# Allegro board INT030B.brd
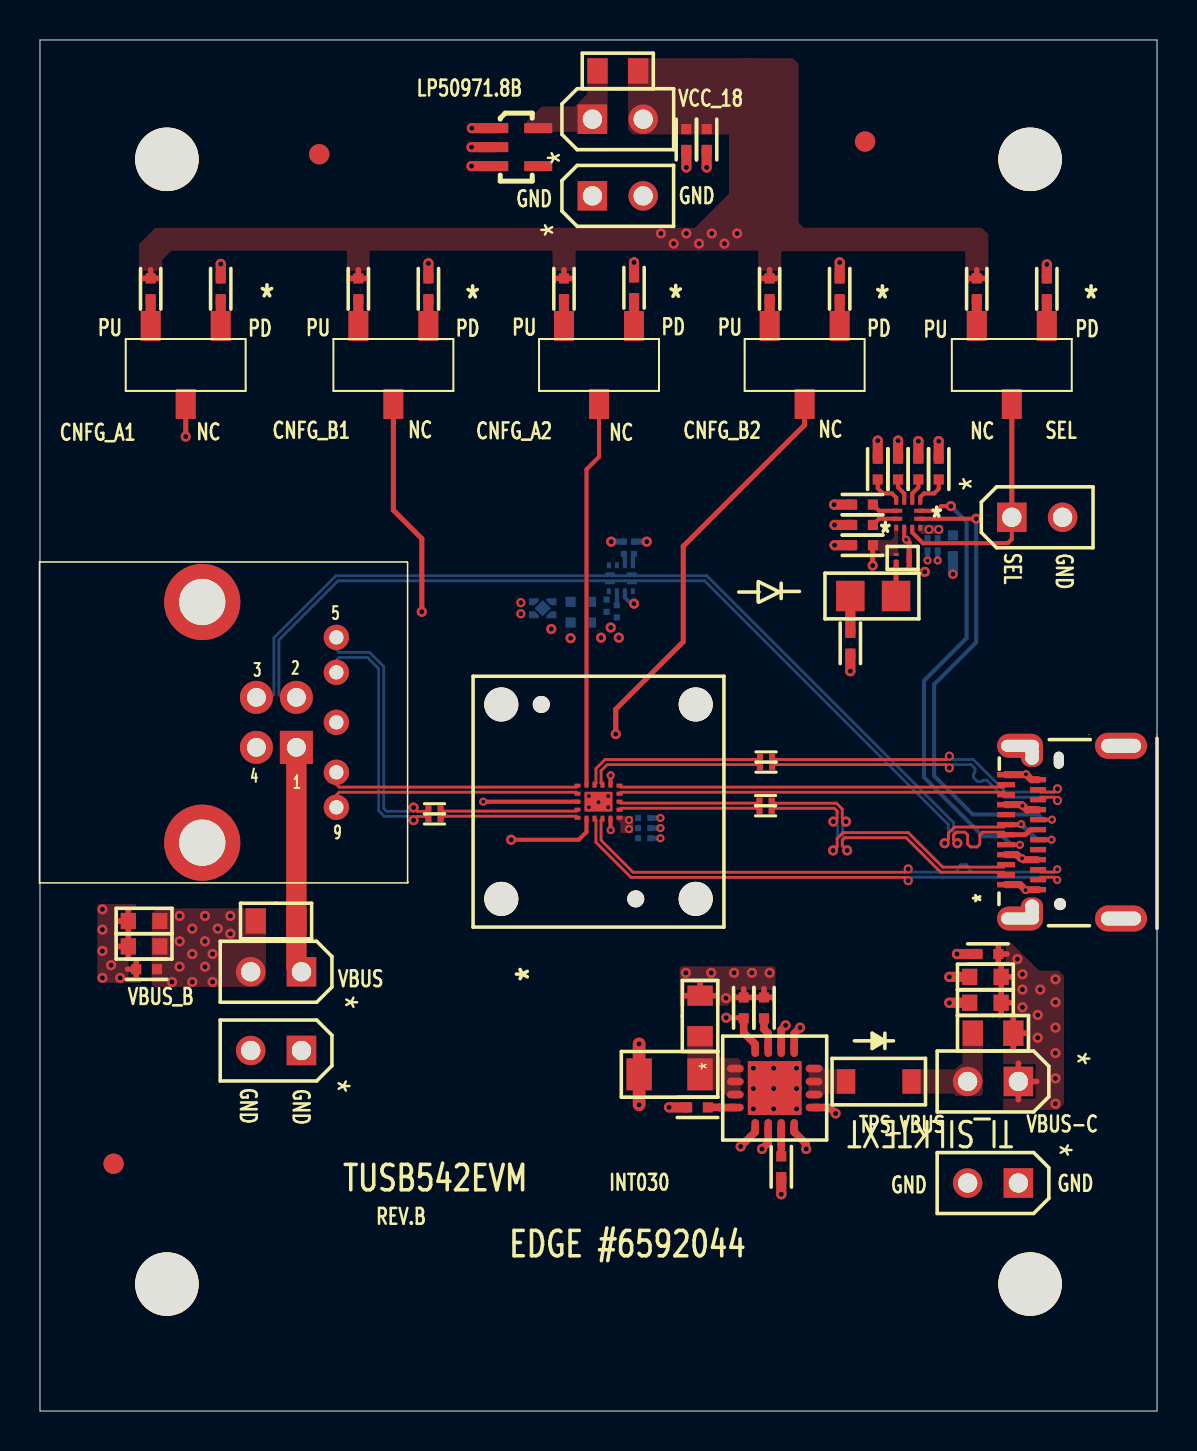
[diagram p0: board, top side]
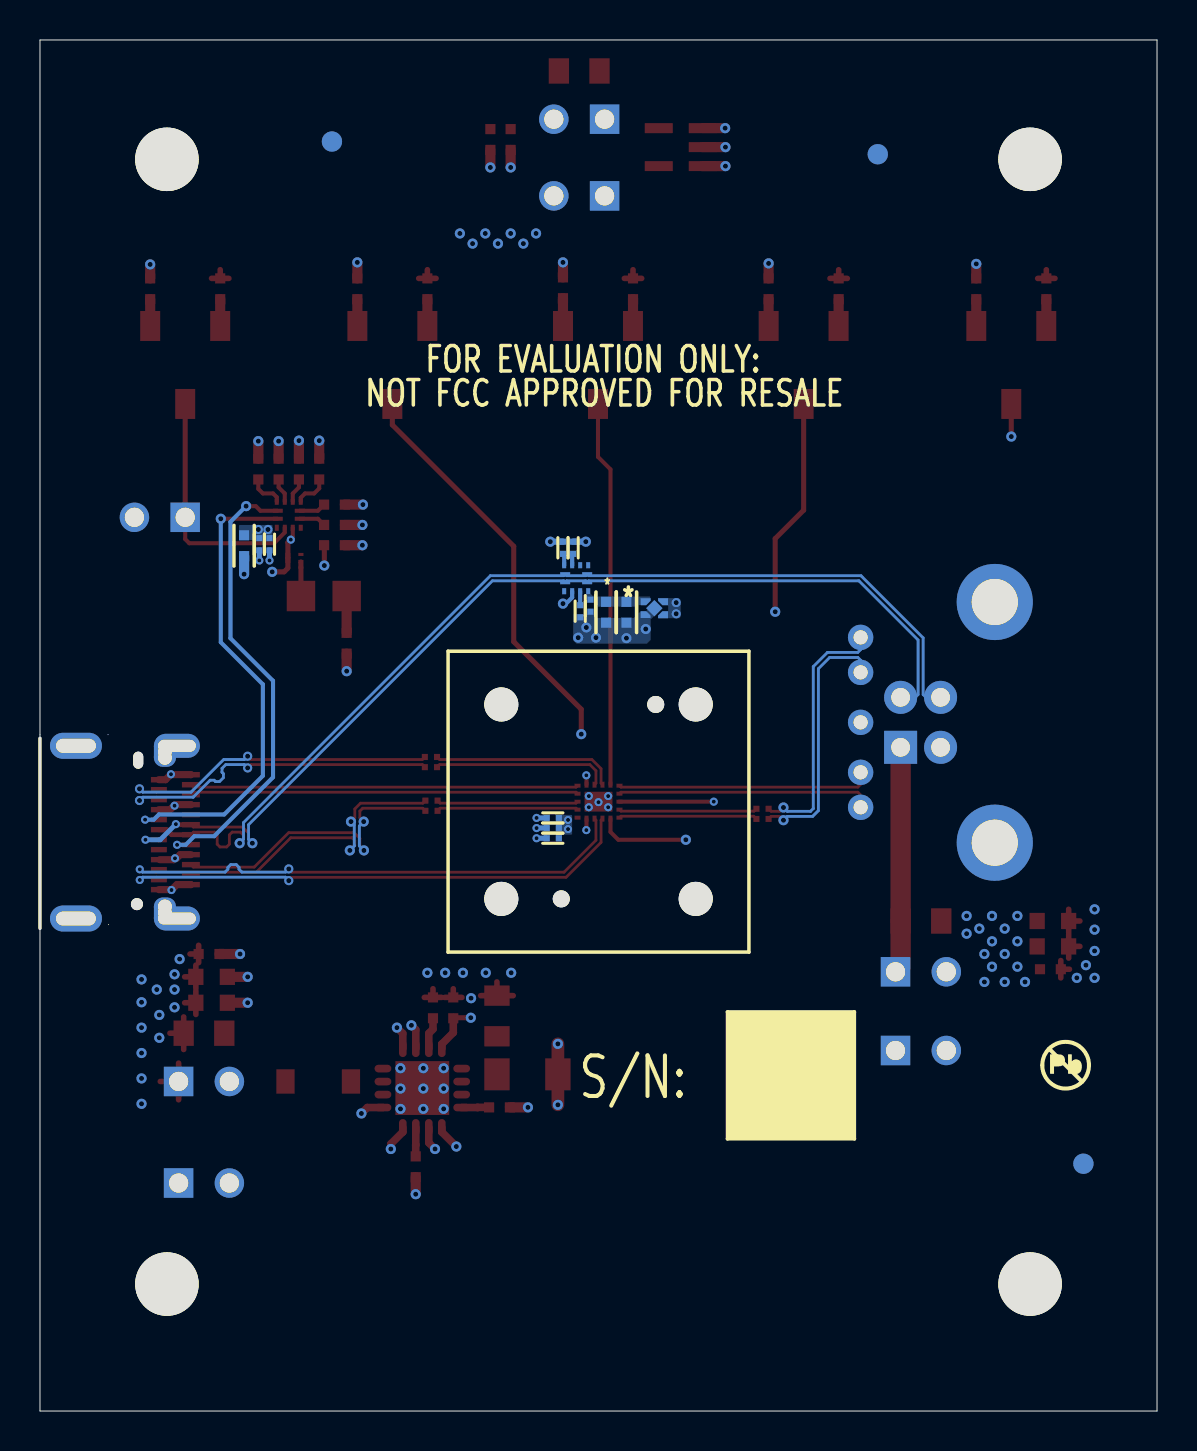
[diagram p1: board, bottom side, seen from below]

Outline 55.88 x 68.58 mm; copper layers: TOP, L2_GND, L3_PWR, L4_PWR, L5_GND, BOTTOM. Coordinates in mm from the lower left corner of the outline.
Outline path: 52.45,24.33 52.45,24.33 ; 52.48,33.83 52.48,33.83 ; 55.88,24.33 55.88,24.33 ; 55.88,33.83 55.88,33.83 ; 0,68.58 55.88,68.58 55.88,0 0,0 0,68.58

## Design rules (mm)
net group RX_AP: nets RX_AP+ RX_AP-
net group SSRX1: nets SSRXN1 SSRXP1
net group SSRX2: nets SSRXN2 SSRXP2
net group SSTX1: nets SSTXN1 SSTXP1
net group SSTX2: nets SSTXN2 SSTXP2
net group TX_AP: nets TX_AP+ TX_AP-
net group TX_AP_CONN: nets TX_AP+_CONN TX_AP-_CONN
net group TX_CON1: nets TX_CON1+ TX_CON1-
net group TX_CON2: nets TX_CON2+ TX_CON2-
net group USB2_D: nets USB2_DM USB2_DP

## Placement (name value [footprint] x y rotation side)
C1  0.1uF  [0201]  19.74 30.12 0 top
C2  0.1uF  [0201]  19.74 29.62 0 top
C3  0.1uF  [0201]  36.3 30.53 0 top
C4  0.1uF  [0201]  36.3 30.02 0 top
C5  0.1uF  [0201]  36.32 32.72 180 top
C6  0.1uF  [0201]  36.32 32.21 180 top
C7  0.01uF  [0201]  30.23 29.67 0 bottom
C8  0.1uF  [0201]  30.23 29.16 0 bottom
C9  0.1uF  [0201]  30.23 28.65 0 bottom
C10  0.1uF  [0402]  33.35 63.6 270 top
C11  1uF  [0402]  32.33 63.6 270 top
C12  10uF  [0603]  5.21 23.24 180 top
C13  10uF  [0603]  5.21 24.51 180 top
C14  1uF  [0402]  5.33 22.1 180 top
C15  10uF  [0603]  47.29 20.42 180 top
C16  10uF  [0603]  47.29 21.72 180 top
C17  1uF  [0402]  47.42 22.86 180 top
C18  1uF  [0402]  45.67 43.28 270 bottom
C19  0.1uF  [0201]  44.91 43.36 270 bottom
C20  0.1uF  [0201]  44.4 43.36 270 bottom
C21  47uF  [1206]  31.5 16.84 180 top
C22  47nF  [0402]  32.89 15.19 180 top
C23  0.1uF  [0201]  28.85 40.01 270 bottom
C24  0.1uF  [0201]  29.21 43.18 90 bottom
C25  0.1uF  [0201]  28.35 40.28 90 bottom
C26  1uF  [0402]  26.54 39.95 270 bottom
C27  1uF  [0402]  27.56 39.95 270 bottom
D1  LED  [LED_0805]  41.68 40.77 180 top
D2  SCHOTTKY  [SOD_123FL]  41.96 16.48 180 top
J1  HDR2X1 M .1  [HDR_THVT_1X2_100]  27.64 64.62 90 top
J2  HDR2X1 M .1  [HDR_THVT_1X2_100]  27.64 60.78 90 top
J3  HDR2X1 M .1  [HDR_THVT_1X2_100]  13.08 21.97 270 top
J4  HDR2X1 M .1  [HDR_THVT_1X2_100]  13.08 18.03 270 top
J5  HDR2X1 M .1  [HDR_THVT_1X2_100]  48.62 44.7 90 top
J6  HDR2X1 M .1  [HDR_THVT_1X2_100]  48.95 16.48 270 top
J7  HDR2X1 M .1  [HDR_THVT_1X2_100]  48.95 11.4 270 top
NOREF  -  []  0 68.28 0 top
NOREF#2  -  []  -20.83 -66.12 0 top
NOREF#3  -  [unnamed#2]  49.53 62.61 0 top
NOREF#4  -  []  -3.81 -69.85 0 top
NOREF#5  -  [unnamed#2]  49.53 6.35 0 top
NOREF#6  -  [unnamed#2]  6.35 6.35 0 top
NOREF#7  -  []  0 0 0 top
NOREF#8  -  [unnamed#2]  6.35 62.61 0 top
NOREF#9  -  [unnamed#2]  3.68 12.37 0 top
NOREF#10  -  [unnamed#2]  13.97 62.87 0 top
NOREF#11  -  []  55.88 0 90 top
NOREF#12  -  []  88.9 38.1 0 top
NOREF#13  -  [unnamed#2]  41.27 63.5 0 top
NOREF#14  -  []  9.93 0.76 0 top
NOREF#15  -  [unnamed#2]  3.68 12.37 180 bottom
NOREF#16  -  []  28.47 16.79 180 bottom
NOREF#17  -  [unnamed#2]  41.27 63.5 180 bottom
NOREF#18  -  [unnamed#2]  13.97 62.87 180 bottom
NOREF#19  -  []  14.45 5.61 180 bottom
P1  USB3.0 Type B Receptacle  [USB3_TYPEB_AK4AA009]  12.83 33.2 270 top
P2  JAE DX07S024JJ2  [TYPEC_JAE_TOPMNT]  51.03 25.35 90 top
Q1  CSD25484 PMOS  [YJJ_DFN_3]  43.15 42.67 0 top
R1  10k  [0402]  5.54 56.13 270 top
R2  10k  [0402]  9.04 56.13 90 top
R3  10k  [0402]  26.21 56.13 270 top
R4  10k  [0402]  29.72 56.18 90 top
R5  10k  [0402]  15.93 56.13 270 top
R6  10k  [0402]  19.43 56.13 90 top
R7  10k  [0402]  36.5 56.13 270 top
R8  10k  [0402]  40.01 56.13 90 top
R9  10k  [0402]  46.86 56.13 270 top
R10  10k  [0402]  50.37 56.13 90 top
R11  10k  [0402]  36.22 20.17 270 top
R12  10k  [0402]  44.96 47.12 270 top
R13  909k  [0402]  42.93 47.12 270 top
R14  499  [0402]  40.54 38.4 90 top
R15  4.7k  [0402]  43.94 47.12 270 top
R16  200k  [0402]  41.91 47.12 270 top
R17  200k  [0402]  41.15 45.34 0 top
R18  200k  [0402]  41.15 44.32 0 top
R19  200k  [0402]  41.15 43.31 0 top
R20  NoPop  [0402]  35.2 20.17 270 top
R21  29.4K  [0402]  37.08 12.22 270 top
R22  0  [0805]  33.02 19.76 270 top
R23  0  [0805]  28.91 67.03 0 top
R24  0  [0805]  11.81 24.51 180 top
R25  0  [0805]  47.68 18.9 180 top
R26  1.6k  [0201]  29.72 43.18 90 bottom
SW1  Switch CJS-1201  [CJS-1200B]  7.29 52.32 270 top
SW2  Switch CJS-1201  [CJS-1200B]  27.97 52.32 270 top
SW3  Switch CJS-1201  [CJS-1200B]  17.68 52.32 270 top
SW4  Switch CJS-1201  [CJS-1200B]  38.25 52.32 270 top
SW5  Switch CJS-1201  [CJS-1200B]  48.62 52.32 270 top
U1  TUSB542RWQ - Ironwood Socket  [SKT_IRONWOOD_C14524]  27.94 30.48 90 top
U2  TUSB321_GPIO  [RWB]  43.43 44.83 180 top
U3  LP5907MFX-1.8NOPB  [DBV_R-PDSO-G5]  23.83 63.22 0 top
U4  TPS25910RSA  [QFN_16_161X161_26]  36.75 16.15 0 top
U5  TUSB211RWB  [RWB]  29.06 41.66 0 bottom
U6  LP5907X2SON  [DQN_X2SON_4]  25.15 40.16 180 bottom

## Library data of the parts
C1-C9 C19 C20 C23-C25 = cc0201
C10 C11 C14 C17 C18 C26 C27 = cc0402
C12 C13 C15 C16 = cc0603
C21 C22 = CAP NP
D1 = d0805 Green
D2 = SCHOTTKY
J1-J7 = HDR2X1 M .1
P1 = USB 3_0.0 Type B Receptacle
P2 = TypeC_JAE_TopMNT_2
Q1 = CSD25484F4
R1-R10 R12-R19 = r0402
R11 R20-R22 = R
R23-R25 = r0805
R26 = r0201
SW1-SW5 = Switch CJS-1201
U1 = TUSB542RWQ
U2 = TUSB321_GPIO
U3 = LP5907
U4 = TPS25910RSA
U5 = TUSB211RWB
U6 = LP5907X2SON

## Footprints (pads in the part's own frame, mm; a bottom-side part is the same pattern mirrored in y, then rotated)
0201
  rect 0.305x0.305 smd: 1(-0.305,0) 2(0.305,0)
0402
  rect 0.508x0.508 smd: 1(-0.521,0) 2(0.521,0)
0603
  rect 0.762x0.813 smd: 1(-0.787,0) 2(0.787,0)
0805
  rect 1.016x1.27 smd: 1(-1.016,0) 2(1.016,0)
1206
  rect 1.27x1.6 smd: 1(-1.524,0) 2(1.524,0)
CJS-1200B
  rect 1.5x1 smd: 1(-1.95,1.75) 2(1.95,0) 3(-1.95,-1.75)
DBV_R-PDSO-G5
  rect 1.4x0.5 smd: 1(-1.1,0.95) 2(-1.1,0) 3(-1.1,-0.95) 4(1.1,-0.95) 5(1.1,0.95)
DQN_X2SON_4
  custom 0.088x0.088 smd: 1(-0.435,0.325) 2(-0.435,-0.325) 3(0.435,-0.325) 4(0.435,0.325)
  rect 0.58x0.58 smd rot 45: 5(0,0)
HDR_THVT_1X2_100
  rect 1.473x1.473 hole 0.965: 1(0,0)
  round 1.473 hole 0.965: 2(0,-2.54)
LED_0805
  rect 1.422x1.524 smd: 1(-1.143,0) 2(1.143,0)
QFN_16_161X161_26
  oval 0.838x0.381 smd: 1(-1.969,0.975) 2(-1.969,0.325) 3(-1.969,-0.325) 4(-1.969,-0.975) 9(1.969,-0.975) 10(1.969,-0.325) 11(1.969,0.325) 12(1.969,0.975)
  oval 0.381x0.838 smd: 5(-0.975,-1.969) 6(-0.325,-1.969) 7(0.325,-1.969) 8(0.975,-1.969) 13(0.975,1.969) 14(0.325,1.969) 15(-0.325,1.969) 16(-0.975,1.969)
  rect 2.692x2.692 smd: 17(0,0)
RWB
  rect 0.5x0.2 smd: 1(-0.55,0.2) 2(-0.55,-0.2) 7(0.55,-0.2) 8(0.55,0.2)
  rect 0.2x0.3 smd: 3(-0.6,-0.65) 4(-0.2,-0.65) 5(0.2,-0.65) 6(0.6,-0.65) 9(0.6,0.65) 10(0.2,0.65) 11(-0.2,0.65) 12(-0.6,0.65)
SKT_IRONWOOD_C14524
  round 1.702 hole 1.702 unplated: (-4.863,4.863) (-4.863,-4.863) (4.863,4.863) (4.863,-4.863)
  round 0.85 hole 0.85 unplated: (-4.863,-1.863) (4.863,2.863)
  rect 0.3x0.2 smd: 1(-0.85,0.6) 2(-0.85,0.2) 3(-0.85,-0.2) 4(-0.85,-0.6) 10(0.85,-0.6) 11(0.85,-0.2) 12(0.85,0.2) 13(0.85,0.6)
  rect 0.2x0.3 smd: 5(-0.8,-1.05) 6(-0.4,-1.05) 7(0,-1.05) 8(0.4,-1.05) 9(0.8,-1.05) 14(0.8,1.05) 15(0.4,1.05) 16(0,1.05) 17(-0.4,1.05) 18(-0.8,1.05)
  rect 0.991x1.397 smd: 19(0,0)
SOD_123FL
  rect 0.914x1.219 smd: 1(-1.638,0) 2(1.638,0)
TYPEC_JAE_TOPMNT
  round 0.6 hole 0.6 unplated: (0,0)
  oval 0.85x0.5 hole 0.85x0.5 unplated: (7.2,0.065)
  rect 0.27x0.9 smd: A1(0.975,2.7) A2(1.475,2.7) A3(1.975,2.7) A4(2.475,2.7) A5(2.975,2.7) A6(3.475,2.7) A7(3.975,2.7) A8(4.475,2.7) A9(4.975,2.7) A10(5.475,2.7) A11(5.975,2.7) A12(6.475,2.7)
  rect 0.27x0.8 smd: B1(6.225,1.1) B2(5.725,1.1) B3(5.225,1.1) B4(4.725,1.1) B5(4.225,1.1) B6(3.725,1.1) B7(3.225,1.1) B8(2.725,1.1) B9(2.225,1.1) B10(1.725,1.1) B11(1.225,1.1) B12(0.725,1.1)
  oval 1.2x2.3 hole 0.6x1.9: C1(-0.72,2) C6(7.92,2)
  rect 0.6x1.1 hole 0.6x0.7: C2(-0.42,1.4) C5(7.62,1.4)
  oval 0.9x1.1 hole 0.7: C3(-0.12,1.4) C4(7.32,1.4)
  oval 1.3x2.6 hole 0.7x2: C7(-0.72,-3.05) C8(7.92,-3.05)
unnamed#2
  round 3.175 hole 3.175 unplated: (0,0)
USB3_TYPEB_AK4AA009
  rect 1.651x1.651 hole 0.94: 1(0,0)
  round 1.651 hole 0.94: 2(-2.5,0) 3(-2.5,-2) 4(0,-2)
  round 1.27 hole 0.711: 5(-5.5,2) 6(-3.75,2) 7(-1.25,2) 8(1.25,2) 9(3,2)
  round 3.81 hole 2.311: 10(-7.27,-4.71) 11(4.77,-4.71)
YJJ_DFN_3
  rect 0.254x0.152 smd: 1(-0.325,0.175) 2(-0.325,-0.175)
  rect 0.254x0.508 smd: 3(0.325,0)

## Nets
3.3V: C25.2 C26.1 C27.1 U5.12(VCC) U6.1(OUT)
GND: C7.2 C8.2 C9.2 C10.2 C11.2 C12.2 C13.2 C14.2 C15.2 C16.2 C17.2 C18.2 C19.2 C20.2 C21.2 C22.2 C23.2 C24.2 C25.1 C26.2 C27.2 J2.1 J2.2 J4.1 J4.2 J5.2 J7.1 J7.2 P1.4(GND) P1.7(GND_DRAIN) P1.10(SHIELD1) P1.11(SHIELD2) P2.A1(GND#A1) P2.A12(GND#A12) P2.B1(GND#B1) P2.B12(GND#B12) P2.C1(CHASSIS#C1) P2.C2(CHASSIS#C2) P2.C3(CHASSIS#C3) P2.C4(CHASSIS#C4) P2.C5(CHASSIS5) P2.C6(CHASSIS6) P2.C7(CHASSIS7) P2.C8(CHASSIS8) Q1.3(DRAIN) R2.2 R4.2 R6.2 R8.2 R10.2 R21.2 R26.2 U1.19(PAD_GND) U2.10(GND) U3.2(GND) U4.5(GND#5) U4.6(GND#6) U4.8(GND#8) U4.9(GND#9) U4.13(GND#13) U4.14(GND#14) U4.17(PWPD) U5.10(GND) U6.2(GND) U6.5(PAD)
VBUS_B: C12.1 C13.1 C14.1 C18.1 C19.1 C20.1 J3.2 R11.1 R12.1 R15.1 R16.1 R17.1 R18.1 R19.1 R20.1 R22.1 R24.2 U2.12(VDD) U3.1(VIN) U3.3(EN) U6.3(EN) U6.4(IN)
VBUS_B_IN: C21.1 R22.2 U4.1(IN#1) U4.2(IN#2) U4.3(IN#3)
VBUS_C: C15.1 C16.1 C17.1 J6.1 P2.A4(VBUS#A4) P2.A9(VBUS#A9) P2.B4(VBUS#B4) P2.B9(VBUS#B9) R13.1 R14.1 R25.1
VBUS_DET: R13.2 U2.5(VBUS_DET)
VCC_18: C7.1 C8.1 C9.1 C10.1 C11.1 J1.2 R1.1 R3.1 R5.1 R7.1 R9.1 R23.2 U1.5(VDD18)
321_ID: Q1.1(GATE) R19.2 R20.2 U2.9(ID) U4.16(EN#)
CC1: P2.A5(CC1) U2.2(CC2)
CC2: P2.B5(CC2) U2.1(CC1)
CNFG_A1: SW1.2 U1.1(CNFG_A1)
CNFG_A2: SW2.2 U1.13(CNFG_A2)
CNFG_B1: SW3.2 U1.4(CNFG_B1)
CNFG_B2: SW4.2 U1.10(CNFG_B2)
CURR_MODE: R12.2 U2.3(CURRENT_MODE)
OUT1: R17.2 U2.7(OUT1)
OUT2: R18.2 U2.8(OUT2)
PORT: R15.2 U2.4(PORT)
RX_AP+: P1.9(SS_RX_P) U1.15(RX_AP+)
RX_AP-: P1.8(SS_RX_N) U1.14(RX_AP-)
SEL: J5.1 SW5.2 U1.16(SEL) U2.11(DIR)
SSRXN1: P2.B10(SSRXN1) U1.3(RX_CON_1-)
SSRXN2: P2.A10(SSRXN2) U1.8(RX_CON_2-)
SSRXP1: P2.B11(SSRXP1) U1.2(RX_CON_1+)
SSRXP2: P2.A11(SSRXP2) U1.9(RX_CON_2+)
SSTXN1: C4.2 P2.A3(SSTXN1)
SSTXN2: C6.1 P2.B3(SSTXN2)
SSTXP1: C3.2 P2.A2(SSTXP1)
SSTXP2: C5.1 P2.B2(SSTXP2)
TX_AP+: C2.2 U1.18(TX_AP+)
TX_AP+_CONN: C2.1 P1.6(SS_TX_P)
TX_AP-: C1.2 U1.17(TX_AP-)
TX_AP-_CONN: C1.1 P1.5(SS_TX_N)
TX_CON1+: C4.1 U1.6(TX_CON_1+)
TX_CON1-: C3.1 U1.7(TX_CON_1-)
TX_CON2+: C5.2 U1.12(TX_CON_2+)
TX_CON2-: C6.2 U1.11(TX_CON_2-)
USB2_DM: P1.2(USB2_DM) P2.A7(DN1) P2.B7(DN2) U5.1(D1M) U5.8(D2M)
USB2_DP: P1.3(USB2_DP) P2.A6(DP1) P2.B6(DP2) U5.2(D1P) U5.7(D2P)
VCONN_FAULT#: R16.2 U2.6(VCONN_FAULT#)
N04611: J3.1 P1.1(VBUS) R24.1
N16552543: R1.2 SW1.3
N16552547: R2.1 SW1.1
N16552551: R3.2 SW2.3
N16552555: R4.1 SW2.1
N16552559: R5.2 SW3.3
N16552563: R6.1 SW3.1
N16552567: R7.2 SW4.3
N16552571: R8.1 SW4.1
N16553344: R10.1 SW5.1
N16553348: R9.2 SW5.3
N16554903: D1.2 R14.2
N16554907: D1.1 Q1.2(SOURCE)
N16595246: R11.2 U4.15(FLT#)
N16595298: D2.2(A) U4.10(OUT#10) U4.11(OUT#11) U4.12(OUT#12)
N16595310: R21.1 U4.7(ILIM)
N16595320: C22.1 U4.4(GATE)
N16602154: J1.1 R23.1 U3.5(VOUT)
N16604263: C23.1 U5.11(VREG)
N16604411: C24.1 U5.5(RSTN)
N16604415: R26.1 U5.6(EQ)
N16616318: D2.1(K) J6.2 R25.2

Pads without a net: P2 A8 B8; U3 4; U5 3 4 9

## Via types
v1: diameter 0.406, hole 0.203, TOP to BOTTOM, 26 vias
v2: diameter 0.508, hole 0.254, TOP to BOTTOM, 112 vias
v3: diameter 0.457, hole 0.254, TOP to BOTTOM, 11 vias

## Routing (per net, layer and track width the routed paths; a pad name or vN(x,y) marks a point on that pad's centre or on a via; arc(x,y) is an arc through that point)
GND: length 169.6
  TOP w0.203: v2(35.69,17.14) 36.75,16.21 U4.17 ; v1(43.33,43.59) 43.33,43.61 43.23,43.71 U2.10
  TOP w0.254: v2(44.26,41.98) 43.67,41.98 43.48,42.16 Q1.3 43.48,43.44 v1(43.33,43.59)
  TOP w0.279: 4.42,22.66 C12.2 ; C12.2 4.42,23.83 ; C12.2 3.86,23.24 ; 4.38,22.1 C14.2 ; C14.2 4.81,21.67 ; C14.2 4.81,22.53 ; P2.C3 P2.C2 ; C13.2 4.42,25.1 ; C13.2 4.42,23.93 ; C13.2 3.86,24.51 ; P2.C4 P2.C5
  TOP w0.356: P2.B1 49.6,31.58 v1(49.33,31.85) 49.31,31.83 48.33,31.83 P2.A12 ; P2.B12 49.32,26.08 v1(49.3,26.06) 49.03,26.33 48.33,26.33 P2.A1
  TOP w0.381: U4.5 35.78,13.96 v2(35.05,13.23) ; U4.8 37.73,13.96 38.33,13.36 v2(38.33,13.11) ; U4.14 37.08,19.07 v2(37.3,19.29) ; v2(36.12,13.11) 36.43,13.42 U4.6 ; U4.13 37.73,18.88 v2(38.02,19.18) ; U4.9 39.51,15.18 v2(39.8,14.88)
  TOP w0.508: R21.2 v2(37.08,10.85) ; C17.2 v2(45.87,22.86) ; R10.2 v2(50.37,57.35) ; C10.2 v2(33.35,62.2) ; R6.2 v2(19.43,57.4) ; C22.2 v2(31.47,15.19) ; R8.2 v2(40.01,57.45) ; C15.2 v2(45.49,20.42) ; R4.2 v2(29.72,57.45) ; U3.2 v2(21.59,63.22) ; R2.2 v2(9.04,57.38) ; C16.2 v2(45.49,21.72) ; C11.2 v2(32.33,62.2)
  TOP w0.635: v2(29.97,18.36) C21.2 v2(29.97,15.32)
  L2_GND w0.279: 50.24,44.7 J5.2 ; J5.2 51.16,45.62 ; J5.2 51.16,43.79 ; J5.2 52.07,44.7 ; 13.08,17.12 J4.1 ; J4.1 13.08,18.95 ; J4.1 14,18.03 ; J4.1 12.17,18.03 ; J7.1 48.95,12.32 ; J7.1 49.86,11.4 ; J7.1 48.95,10.49 ; J7.1 48.03,11.4 ; 14.01,34.45 P1.7 ; P1.7 14.83,35.26 ; P1.7 14.83,33.63 ; P1.7 15.64,34.45 ; J2.2 30.18,61.7 ; J2.2 29.26,60.78 ; J2.2 30.18,59.87 ; J2.2 31.09,60.78 ; J7.2 46.41,12.32 ; J7.2 47.32,11.4 ; J7.2 45.49,11.4 ; J7.2 46.41,10.49 ; 49.03,23.86 P2.C1 ; P2.C1 47.7,24.63 ; P2.C1 50.36,24.63 ; P2.C7 54.08,25.46 ; P2.C7 54.08,23.81 ; P2.C7 52.6,24.63 ; P1.11 10.2,28.43 ; P1.11 8.12,26.34 ; P1.11 6.03,28.43 ; P1.11 8.12,30.51 ; 49.63,25.86 P2.C3 50.36,25.23 ; 52.6,33.27 P2.C8 ; P2.C8 54.08,34.1 ; P2.C8 54.08,32.45 ; P1.4 10.83,34.2 ; P1.4 9.82,33.2 ; P1.4 10.83,32.19 ; J4.2 10.54,18.95 ; J4.2 9.63,18.03 ; J4.2 10.54,17.12 ; J4.2 11.46,18.03 ; P2.C6 50.36,33.27 ; P2.C6 49.03,34.05 ; P2.C6 47.7,33.27 ; 26.72,60.78 J2.1 ; J2.1 28.55,60.78 ; J2.1 27.64,59.87 ; J2.1 27.64,61.7 ; 6.03,40.47 P1.10 ; P1.10 8.12,38.38 ; P1.10 10.2,40.47 ; P1.10 8.12,42.55 ; 50.36,32.67 P2.C4 49.63,32.05
  L5_GND w0.279: 10.83,32.19 P1.4 ; P1.4 10.83,34.2 ; P1.4 9.82,33.2 ; J4.1 13.08,18.95 ; J4.1 14,18.03 ; J4.1 12.17,18.03 ; J4.1 13.08,17.12 ; 54.08,23.81 P2.C7 ; P2.C7 52.6,24.63 ; P2.C7 54.08,25.46 ; 45.49,11.4 J7.2 ; J7.2 47.32,11.4 ; J7.2 46.41,10.49 ; J7.2 46.41,12.32 ; P1.7 14.83,35.26 ; P1.7 14.83,33.63 ; P1.7 15.64,34.45 ; P1.7 14.01,34.45 ; P1.11 10.2,28.43 ; P1.11 8.12,26.34 ; P1.11 6.03,28.43 ; P1.11 8.12,30.51 ; 50.36,32.67 P2.C4 49.63,32.05 ; 47.7,33.27 P2.C6 ; P2.C6 50.36,33.27 ; P2.C6 49.03,34.05 ; 9.63,18.03 J4.2 ; J4.2 10.54,18.95 ; J4.2 11.46,18.03 ; J4.2 10.54,17.12 ; 26.72,60.78 J2.1 ; J2.1 27.64,61.7 ; J2.1 28.55,60.78 ; J2.1 27.64,59.87 ; P1.10 8.12,42.55 ; P1.10 6.03,40.47 ; P1.10 8.12,38.38 ; P1.10 10.2,40.47 ; 54.08,32.45 P2.C8 ; P2.C8 54.08,34.1 ; P2.C8 52.6,33.27 ; J7.1 49.86,11.4 ; J7.1 48.95,12.32 ; J7.1 48.03,11.4 ; J7.1 48.95,10.49 ; P2.C1 50.36,24.63 ; P2.C1 49.03,23.86 ; P2.C1 47.7,24.63 ; J5.2 52.07,44.7 ; J5.2 51.16,43.79 ; J5.2 50.24,44.7 ; J5.2 51.16,45.62 ; 49.63,25.86 P2.C3 50.36,25.23 ; J2.2 31.09,60.78 ; J2.2 30.18,61.7 ; J2.2 29.26,60.78 ; J2.2 30.18,59.87
  BOTTOM w0.203: U5.10 29.26,40.69 29.57,40.39 v2(29.72,40.39)
  BOTTOM w0.254: C20.2 v1(44.4,42.55) ; C9.2 v1(31.04,28.65) ; C7.2 v1(31.04,29.67) ; C19.2 v1(44.91,42.55) ; C8.2 v1(31.04,29.16)
  BOTTOM w0.305: C24.2 v2(28.57,43.48) ; R26.2 v2(30.35,43.48)
  BOTTOM w0.508: C18.2 v3(45.67,41.86)
  vias: v1(27.46,30.76) v1(27.46,30.2) v1(27.94,30.45) v1(28.42,30.76) v1(28.42,30.2) v2(3.12,25.1) v2(3.12,24.08) v2(3.12,23.01) v2(3.12,21.67) v2(3.56,22.3) v2(4.01,21.67) v2(25.58,39.12) v2(26.54,38.66) v2(28.07,38.68) v2(28.55,39.19) v2(28.96,38.68) v2(35.69,16.13) v2(35.69,15.11) v2(36.7,17.14) v2(36.7,16.13) v2(36.7,15.11) v2(37.85,17.14) v2(37.85,16.13) v2(37.85,15.11)
VBUS_B: length 16.1
  TOP w0.279: R11.1 36.65,20.69 ; R11.1 35.79,20.69 ; R11.1 36.22,21.12 ; 34.77,20.69 R20.1 ; R20.1 35.2,21.12 ; R20.1 35.64,20.69 ; R22.1 33.02,21.46 ; R22.1 32.21,20.78 ; R22.1 33.83,20.78
  TOP w0.508: R15.1 v2(43.94,48.51) ; R12.1 v2(44.96,48.51) ; R17.1 v2(39.73,45.34) ; R16.1 v2(41.91,48.54) ; R18.1 v2(39.75,44.32) ; U3.3 v2(21.59,62.27) ; R19.1 v2(39.75,43.31) ; U3.1 v2(21.61,64.17)
  L3_PWR w0.279: J3.2 10.54,22.89 ; J3.2 9.63,21.97 ; J3.2 10.54,21.06 ; J3.2 11.46,21.97
  vias: v2(6.6,21.46) v2(6.99,24.77) v2(6.99,23.5) v2(6.99,22.23) v2(7.62,24.13) v2(7.62,22.86) v2(7.62,21.46) v2(8.26,24.77) v2(8.26,23.5) v2(8.26,22.23) v2(8.64,22.86) v2(8.64,21.46) v2(8.89,24.13) v2(9.53,24.77) v2(9.53,23.88) v2(32.31,21.92) v2(33.58,21.92) v2(34.32,20.65) v2(34.72,21.92) v2(35.61,21.92) v2(36.5,21.92) v3(24.05,40.44) v3(24.05,39.88) v3(44.48,44.09) v3(44.96,44.09)
VBUS_C: length 18.7
  TOP w0.14: P2.B9 49.93,27.58 49.88,27.58
  TOP w0.279: 47.94,22.43 C17.1 ; C17.1 48.37,22.86 ; C17.1 47.94,23.29 ; J6.1 48.95,17.4 ; J6.1 49.86,16.48 ; J6.1 48.95,15.57 ; 48.69,18.08 R25.1 ; R25.1 48.69,19.71 ; R25.1 49.38,18.9 ; 48.08,21.13 C16.1 ; C16.1 48.08,22.3 ; C16.1 48.64,21.72 ; 48.08,19.84 C15.1 ; C15.1 48.64,20.42 ; C15.1 48.08,21.01
  TOP w0.356: P2.B4 49.37,30.08 49.23,30.23 49.2,30.23 v1(49.15,30.28) 49.09,30.33 48.33,30.33 P2.A9 ; 49.88,27.58 49.2,27.58 v1(49.13,27.65) 49.05,27.65 48.87,27.83 P2.A4
  TOP w0.508: R14.1 v2(40.54,37.01) ; R13.1 v2(42.93,48.54)
  L4_PWR w0.279: J6.1 49.86,16.48 ; J6.1 48.95,17.4 ; J6.1 48.03,16.48 ; J6.1 48.95,15.57
  vias: v2(48.9,22.61) v2(49.15,21.84) v2(49.15,21.08) v2(49.15,20.19) v2(49.91,19.81) v2(49.91,18.67) v2(50.04,21.08) v2(50.8,21.59) v2(50.8,20.45) v2(50.8,19.18) v2(50.8,17.91) v2(50.8,16.64) v2(50.8,15.37)
VBUS_DET: length 1.2
  TOP w0.203: U2.5 43.23,45.89 42.93,46.2 R13.2
VCC_18: length 6.5
  TOP w0.279: R7.1 36.93,56.65 ; R7.1 36.5,57.09 ; R7.1 36.07,56.65 ; R3.1 26.65,56.65 ; R3.1 26.21,57.09 ; R3.1 25.78,56.65 ; 5.1,56.65 R1.1 ; R1.1 5.54,57.09 ; R1.1 5.97,56.65 ; R9.1 46.86,57.09 ; R9.1 46.43,56.65 ; R9.1 47.3,56.65 ; R5.1 16.36,56.65 ; R5.1 15.49,56.65 ; R5.1 15.93,57.09
  vias: v1(29.46,29.57) v1(29.46,29.11) v2(31.06,58.9) v2(31.7,58.39) v2(32.33,58.9) v2(32.97,58.39) v2(33.6,58.9) v2(34.24,58.39) v2(34.87,58.9)
321_ID: length 31.9
  TOP w0.254: v2(34.33,19.67) 35.2,19.67 ; R19.2 41.66,43.29 v2(41.66,42.29)
  TOP w0.381: U4.16 35.78,18.35 35.2,18.93 R20.2 35.2,19.67
  L4_PWR w0.254: v2(41.66,42.29) 39.47,42.29 37.57,40.39 37.57,20.8 36.44,19.67 v2(34.33,19.67)
CC1: length 23.4
  TOP w0.14: P2.A5 48.32,28.32
  TOP w0.203: U2.2 44.85,45.03 45.09,45.26 v2(45.57,45.26) ; 48.32,28.32 v1(49.02,28.32)
  BOTTOM w0.203: v2(45.57,45.26) 46.35,44.48 46.35,38.66 44.22,36.53 44.22,31.7 47.17,28.75 48.16,28.75 48.59,28.32 v1(49.02,28.32)
CC2: length 24.1
  TOP w0.14: P2.B5 49.94,29.57
  TOP w0.203: v1(50.62,29.58) 50.62,29.57 49.94,29.57 ; U2.1 v2(46.83,44.63)
  BOTTOM w0.203: v1(50.62,29.58) 50.19,29.58 49.93,29.84 46.67,29.84 44.73,31.78 44.73,36.35 46.83,38.45 v2(46.83,44.63)
CNFG_A1: length 38.2
  TOP w0.203: v2(23.57,28.57) 26.95,28.57 27.34,28.97 U1.1
  TOP w0.254: SW1.2 v2(7.29,48.74)
  L4_PWR w0.254: v2(7.29,48.74) 7.29,47.19 9.14,45.34 16.18,45.34 20.19,41.33 20.19,30.35 21.97,28.57 v2(23.57,28.57)
CNFG_A2: length 19.3
  TOP w0.203: U1.13 27.34,47.1 27.97,47.73 SW2.2
CNFG_B1: length 32.8
  TOP w0.203: U1.4 28.54,29.07 v1(28.55,29.06)
  TOP w0.254: SW3.2 17.68,45.06 19.1,43.64 v2(19.1,39.98)
  L4_PWR w0.254: v2(19.1,39.98) 19.46,39.62 19.46,29.23 21.06,27.64 27.13,27.64 v1(28.55,29.06)
CNFG_B2: length 23.1
  TOP w0.203: U1.10 28.54,31.77 28.55,31.78 v1(28.55,31.8)
  TOP w0.254: v2(28.8,33.86) 28.8,35.1 32.18,38.48 32.18,43.26 38.25,49.33 SW4.2
  L4_PWR w0.254: v1(28.55,31.8) 28.55,32.44 28.8,32.69 v2(28.8,33.86)
CURR_MODE: length 1.8
  TOP w0.203: R12.2 44.96,46.13 44.73,45.9 44.22,45.9 44.03,45.71 U2.3
OUT1: length 1.3
  TOP w0.203: U2.7 41.98,45.03 R17.2
OUT2: length 1.3
  TOP w0.203: R18.2 41.98,44.63 U2.8
PORT: length 1.2
  TOP w0.203: U2.4 43.63,45.89 43.94,46.2 R15.2
RX_AP+: length 12.8
  TOP w0.14: U1.15 26.82,30.95 14.97,30.95 14.83,30.81 P1.9
RX_AP-: length 12.8
  TOP w0.14: U1.14 26.82,31.21 14.97,31.21 14.83,31.35 P1.8
SEL: length 63.9
  TOP w0.203: J5.1 48.62,43.61 48.41,43.41 44.17,43.41 43.63,43.95 U2.11 ; U1.16 v1(22.17,30.48)
  TOP w0.254: SW5.2 J5.1
  L4_PWR w0.254: v1(22.17,30.48) 21.36,30.48 21.03,30.81 21.03,40.44 30.51,49.91 47.4,49.91 48.62,48.69 J5.1
SSRXN1: length 26.3
  TOP w0.14: v1(50.89,27.1) 50.75,26.96 50.05,26.96 P2.B10 ; v3(43.43,27.12) 43.27,26.95 29.67,26.95 28.07,28.55 28.07,29.56 U1.3
  BOTTOM w0.14: v1(50.89,27.1) 50.75,26.96 46.62,26.96 46.48,27.1 46.48,27.19 46.34,27.33 46.06,27.33 45.92,27.19 45.92,27.1 45.78,26.96 43.59,26.96 v3(43.43,27.12)
SSRXN2: length 19.4
  TOP w0.14: U1.8 29.06,30.95 48.21,30.95 P2.A10
SSRXP1: length 26.3
  TOP w0.14: U1.2 27.81,29.56 27.81,28.44 29.56,26.7 43.27,26.7 v3(43.43,26.53) ; v1(50.89,26.56) 50.75,26.7 50.05,26.7 P2.B11
  BOTTOM w0.14: v3(43.43,26.53) 43.61,26.7 50.75,26.7 v1(50.89,26.56)
SSRXP2: length 19.4
  TOP w0.14: U1.9 29.06,31.21 48.21,31.21 P2.A11
SSTXN1: length 15.6
  TOP w0.14: v2(39.67,28.04) 39.88,28.24 39.88,28.64 40.17,28.93 43.44,28.93 45.16,27.21 48.21,27.21 P2.A3 ; v2(39.69,29.48) 39.88,29.67 39.88,30.01 39.74,30.15 36.73,30.15 C4.2
  BOTTOM w0.14: v2(39.67,28.04) 39.9,28.27 39.9,29.27 v2(39.69,29.48)
SSTXN2: length 16.7
  TOP w0.14: v3(45.49,32.17) 45.33,32.33 36.75,32.33 C6.1 ; v3(50.9,30.54) 50.74,30.7 50.05,30.7 P2.B3
  BOTTOM w0.14: v3(50.9,30.54) 50.74,30.7 48.22,30.7 47.37,31.55 47.17,31.55 47.1,31.48 46.9,31.48 46.7,31.68 46.7,31.88 46.77,31.95 46.77,32.14 46.58,32.33 45.66,32.33 v3(45.49,32.17)
SSTXP1: length 15.6
  TOP w0.14: v2(40.32,29.48) 40.13,29.67 40.13,30.12 39.84,30.4 36.73,30.4 C3.2 ; P2.A2 48.21,26.95 45.06,26.95 43.33,28.68 40.27,28.68 40.13,28.54 40.13,28.29 v2(40.38,28.04)
  BOTTOM w0.14: v2(40.38,28.04) 40.16,28.26 40.16,29.32 v2(40.32,29.48)
SSTXP2: length 16.3
  TOP w0.14: v3(50.9,31.12) 50.74,30.96 50.05,30.96 P2.B2 ; C5.1 36.75,32.59 45.33,32.59 v3(45.49,32.75)
  BOTTOM w0.14: v3(50.9,31.12) 50.74,30.96 48.32,30.96 46.69,32.59 45.66,32.59 v3(45.49,32.75)
TX_AP+: length 6.9
  TOP w0.14: U1.18 26.82,29.75 20.18,29.75 C2.2
TX_AP+_CONN: length 12.9
  TOP w0.14: v2(18.69,29.55) 18.88,29.74 19.3,29.74 C2.1
  BOTTOM w0.14: P1.6 14.83,37.55 14.97,37.69 16.38,37.69 16.94,37.13 16.94,30.03 17.23,29.74 18.5,29.74 v2(18.69,29.55)
TX_AP-: length 6.9
  TOP w0.14: U1.17 26.82,30.01 20.16,30.01 C1.2
TX_AP-_CONN: length 12.9
  TOP w0.14: v2(18.69,30.19) 18.88,30 19.3,30 C1.1
  BOTTOM w0.14: P1.5 14.83,38.7 14.83,38.09 14.97,37.95 16.48,37.95 17.2,37.24 17.2,30.14 17.33,30 18.5,30 v2(18.69,30.19)
TX_CON1+: length 7.1
  TOP w0.14: U1.6 29.06,30.15 35.86,30.15 C4.1
TX_CON1-: length 7.1
  TOP w0.14: C3.1 35.87,30.41 29.06,30.41 U1.7
TX_CON2+: length 9.3
  TOP w0.14: U1.12 27.81,31.4 27.81,32.13 28.27,32.59 35.89,32.59 C5.2
TX_CON2-: length 8.9
  TOP w0.14: U1.11 28.07,31.4 28.07,32.03 28.38,32.33 35.89,32.33 C6.2
USB2_DM: length 51.5
  TOP w0.14: P2.A7 48.21,29.21 45.75,29.21 45.45,28.91 45.45,28.59 v2(45.26,28.4)
  TOP w0.241: P2.B7 49.93,28.57 v1(50.6,28.57) ; P2.A7 49.05,29.33 v1(49.08,29.36)
  BOTTOM w0.14: P1.2 12.09,35.7 11.95,35.84 11.95,38.57 14.91,41.53 28.43,41.53 U5.1 28.58,41.53 29.53,41.53 U5.8 29.68,41.53 33.24,41.53 45.45,29.33 45.45,28.59 v2(45.26,28.4)
  BOTTOM w0.241: v1(49.08,29.36) 49.86,28.57 v1(50.6,28.57)
USB2_DP: length 51.5
  TOP w0.14: v2(45.89,28.4) 45.7,28.59 45.7,28.8 45.85,28.96 46.27,28.96 46.41,28.82 46.41,28.35 46.55,28.21 46.88,28.21 47.02,28.35 47.02,28.82 47.16,28.96 48.2,28.96 P2.A6
  TOP w0.241: P2.A6 49.29,28.83 49.54,29.08 P2.B6
  BOTTOM w0.14: P1.3 11.56,35.7 11.7,35.84 11.7,38.67 14.81,41.78 28.43,41.78 U5.2 28.58,41.78 29.53,41.78 U5.7 29.68,41.78 33.35,41.78 45.7,29.43 45.7,28.59 v2(45.89,28.4)
VCONN_FAULT#: length 1.8
  TOP w0.203: U2.6 42.83,45.68 42.62,45.9 42.16,45.9 41.91,46.15 R16.2
N04611: length 11.3
  TOP w1.016: J3.1 12.83,22.23 R24.1 P1.1
N16552543: length 1.3
  TOP w0.508: SW1.3 5.54,54.28 R1.2
N16552547: length 1.3
  TOP w0.508: SW1.1 9.04,54.28 R2.1
N16552551: length 1.3
  TOP w0.508: R3.2 26.21,54.28 SW2.3
N16552555: length 1.4
  TOP w0.508: SW2.1 29.72,54.28 R4.1
N16552559: length 1.3
  TOP w0.508: R5.2 15.93,54.28 SW3.3
N16552563: length 1.3
  TOP w0.508: SW3.1 19.43,54.28 R6.1
N16552567: length 1.3
  TOP w0.508: SW4.3 36.5,54.28 R7.2
N16552571: length 1.3
  TOP w0.508: R8.1 40.01,54.28 SW4.1
N16553344: length 1.3
  TOP w0.508: SW5.1 50.37,54.28 R10.1
N16553348: length 1.3
  TOP w0.508: R9.2 46.86,54.28 SW5.3
N16554903: length 1.8
  TOP w0.508: R14.2 D1.2
N16554907: length 1.7
  TOP w0.203: 42.82,42.19 42.83,42.19 ; 42.83,42.4 Q1.2
  TOP w0.254: D1.1 42.82,42.19 ; 42.83,42.19 42.83,42.4
N16595246: length 1.6
  TOP w0.381: 36.22,19.67 R11.2 36.22,19.1 36.43,18.89 U4.15
N16595310: length 1.4
  TOP w0.381: R21.1 37.08,13.31 37.08,13.31 U4.7
N16595320: length 1.4
  TOP w0.381: U4.4 34,15.18 33.99,15.19 C22.1
N16604263: length 0.7
  BOTTOM w0.203: U5.11 28.86,40.31 C23.1
N16604411: length 0.6
  BOTTOM w0.203: C24.1 29.26,42.83 U5.5
N16604415: length 0.6
  BOTTOM w0.203: R26.1 29.66,42.81 U5.6

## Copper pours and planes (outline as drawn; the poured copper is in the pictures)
3.3V on BOTTOM: 25.35,40.51 25.35,40.72 25.37,40.74 28.19,40.74 28.35,40.89 28.35,41.15 28.55,41.15 28.55,40.46 28.52,40.44 28.17,40.44 27.97,40.23 26.01,40.23 25.93,40.31 25.55,40.31
GND on TOP: 4.8,25.36 2.95,25.36 2.87,25.28 2.87,21.54 2.98,21.42 5.05,21.42 5.05,22.58 4.8,22.83
GND on BOTTOM: 29.21,39.83 29.18,39.85 28.6,39.85 28.5,39.95 28.5,40.13 28.19,40.13 28.19,39.83 28.04,39.67 26.16,39.67 25.83,40.01 25.56,40.01 25.19,40.38 24.87,40.06 25.32,39.6 25.32,38.57 25.52,38.38 29.05,38.38 29.21,38.55
GND on L2_GND, L5_GND: 0.64,0.64 0.64,67.94 55.24,67.94 55.24,34.34 55.24,23.83 55.24,0.64
VBUS_B on TOP: 32,20.27 32,22.16 32.1,22.25 36.72,22.25 36.79,22.18 36.79,20.47 34.59,20.47 34.39,20.27
VBUS_B on TOP: 11.3,25.15 5.84,25.15 5.59,24.89 5.59,21.34 5.71,21.21 10.92,21.21 11.3,21.59
VBUS_B on BOTTOM: 44.25,43.51 44.25,44.3 44.27,44.32 45.9,44.32 45.92,44.3 45.92,43.56 45.26,43.56 45.21,43.51
VBUS_B on BOTTOM: 24.94,40.67 23.93,40.67 23.83,40.57 23.83,39.73 23.91,39.65 24.94,39.65 24.94,39.78 24.71,40.01 24.46,40.01 24.46,40.31 24.71,40.31 24.94,40.54
VBUS_B on L3_PWR: 0.64,0.64 0.64,67.94 55.24,67.94 55.24,34.47 55.24,23.7 55.24,0.64
VBUS_B_IN on TOP: 32.38,19.25 32.38,16.05 34.06,16.05 34.47,15.65 35.05,15.65 35.05,17.55 34.95,17.65 34.11,17.65 33.66,18.11 33.66,19.25
VBUS_C on TOP: 47.7,23.44 47.7,19.89 48.18,19.41 48.18,15.06 50.93,15.06 51.23,15.37 51.23,21.77 50.98,22.02 49.99,22.02 48.56,23.44
VBUS_C on L4_PWR: 51.05,15.24 50.93,15.11 48,15.11 47.73,15.39 47.73,18.44 45.85,20.32 45.85,32.86 43.4,35.31 40.45,35.31 39.49,36.27 39.49,39.01 42.16,41.66 42.16,48.9 42.49,49.28 45.96,49.28 47.24,48 47.24,37.31 51.05,33.53
VCC_18 on TOP: 29.41,67.67 29.41,64.11 29.67,63.86 35.76,63.86 35.89,63.98 35.89,67.54 35.76,67.67
VCC_18 on TOP: 4.95,56.41 4.95,58.37 5.77,59.18 32.76,59.18 34.47,60.89 34.47,67.12 35.02,67.67 37.67,67.67 37.95,67.39 37.95,59.45 38.21,59.19 47.11,59.19 47.44,58.86 47.44,56.41 46.29,56.41 46.29,57.96 46.23,58.01 37.13,58.01 37.08,57.96 37.08,56.39 35.93,56.39 35.93,58 35.89,58.04 26.82,58.04 26.8,58.01 26.8,56.41 25.64,56.41 25.64,58 25.6,58.04 16.51,58.04 16.49,58.03 16.49,56.41 15.35,56.41 15.35,58.01 15.32,58.04 6.58,58.04 6.12,57.58 6.12,56.41
VCC_18 on BOTTOM: 30.07,29.82 30.07,28.5 29.77,28.5 29.77,28.8 29.74,28.83 29.29,28.83 29.26,28.85 29.26,29.79 29.29,29.82
VCC_18 on L3_PWR: 29.21,28.32 29.08,28.45 29.08,37.34 30.73,38.98 30.73,59.18 35.19,59.18 35.19,34.01 30.73,29.84 30.73,28.32
321_ID on TOP: 42.93,44.32 42.93,43 42.95,42.98 42.95,42.77 42.19,42.77 41.91,43.05 41.43,43.05 41.43,43.56 42.57,43.56 42.72,43.71 42.72,44.32
N16595298 on TOP: 40.79,17.09 39.27,17.09 39.04,17.32 38.46,17.32 38.46,15.65 39.04,15.65 39.27,15.88 40.77,15.88 40.79,15.9
N16602154 on TOP: 24.33,63.98 28.4,63.98 28.4,67.67 27.38,67.67 27.38,65.89 26.87,65.38 26.87,65.38 26.75,65.25 25.09,65.25 24.33,64.49
N16616318 on TOP: 43.15,17.09 45.77,17.09 46.15,17.42 46.15,19.53 47.17,19.53 47.17,15.88 47.04,15.75 45.82,15.75 45.69,15.88 43.15,15.88

Small or netless copper shapes (teardrops, artwork), in the pictures only: 2 on TOP

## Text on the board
BOTTOM: LAYER 4 - BOTTOM SIDE
Board Geometry/Soldermask Bottom: SOLDERMASK BOTTOM
Package Geometry/Pastemask Bottom: PASTEMASK BOTTOM
Ref Des/Silkscreen Bottom: * | FOR EVALUATION ONLY: | NOT FCC APPROVED FOR RESALE | SILKSCREEN BOTTOM
TOP: LAYER 1 - TOP SIDE
Ref Des/Assembly Top: *
Board Geometry/Soldermask Top: SOLDERMASK TOP
Package Geometry/Pastemask Top: PASTEMASK TOP
Ref Des/Silkscreen Top: CNFG_A1 | PU | VBUS_B | NC | PD | CNFG_B1 | VBUS | REV.B | LP50971.8B | CNFG_A2 | GND | INT030 | VCC_18 | CNFG_B2 | TPS_VBUS | VBUS-C | SEL | * | TUSB542EVM | EDGE #6592044 | SILKSCREEN TOP
L2_GND: LAYER 2 - GND PLANE
L3_PWR: LAYER 3 - PWR PLANE
L4_PWR: LAYER 4  -  PWR
L5_GND: LAYER 5  -  GND PLANE
XSECTION_CHART: * AIR 0 MIL | * SOLDERMASK-0.8MIL 0.8 MIL | L1: COPPER_1/2OZ_PLATED 1.4 MIL | * FILL_0.150 5.91 MIL | L2: COPPER_1.0OZ 1.2 MIL | * CORE_1.10 5.91 MIL | L3: COPPER_1.0OZ 1.2 MIL | * AIR 29.16 MIL | L4: COPPER 1.2 MIL | * AIR 5.91 MIL | L5: COPPER 1.2 MIL | L6: COPPER_1/2OZ_PLATED 1.4 MIL | DESIGN CROSS SECTION CHART | ___________________________ | TOTAL THICKNESS 62 MIL | 1-6
DIMENSION: FABRICATION DRAWING | CAD ORIGIN
User.6: LAYER 1 | LAYER 2 | LAYER 3 | LAYER 4 | LAYER 5 | LAYER 6 | LAYER | NO. | TABLE 1: | TOP | L2_GND | L3_PWR | L4_PWR | L5_GND | BOTTOM | NAME | DIFFIRENTIAL PAIR | IMPEDANCE (OHMS) | 90  +/- 10% | DIFF TRACE | WIDTH | 0.0055" | SPACING | 0.0045" | SINGLE ENDED | TRACE WIDTH | REFERENCE | DRILL CHART: | SPECIAL FAB NOTES: | 1:FAB SHOP MUST FOLLOW THE SOLDER MASK REVIEW LAYERS. | MIN. ANNULAR RING 2 MIL EXTERNAL PER IPC-6012C CLASS 2 | REGISTRATION TOLERANCES: METAL +/- X MIL,HOLES +/- X MIL | IMPEDANCE CONTROL: | BOARD SIZE (REFER ALSO ARRAY/PANEL PROFILING INFORMATION) | MIXED DIELECTRIC: | LAMINATE MATERIAL: | THICKNESS: | TOLERANCE: | COPPER THICKNESS (FINISHED): | BOARD FINISH: | NUMBER OF LAYERS: | MIN. TRACK WIDTH: | MIN. CLEARANCE  : | MIN. VIA PAD/DRILL: | THIEVING ALLOWED: | X | OUTER: | INNER SIGNAL: | INNER PLANE: | OTHER: | SILKSCREEN: | SOLDERMASK: (PER IPC-6011,6012) | BOARD SURFACE TREATMENT: | ADDITIONAL REQUIREMENTS: | VENDOR MARKING: | SILKSCREEN COLOR: | SOLDERMASK COLOR: | THROUGH-HOLE VIA TREATMENT: | VIA FILL USING NON-CONDUCTIVE EPOXY: | FOR WIRE BONDING: | VENDOR DATE CODE,UL,LOGO: | FR-4 HIGH Tg | 0.062" +/-10% | IPC-6012C TYPE 3 CLASS 2 | OTHER +/- | MICRO-SECTION | CERTIFICATES OF COMPLIANCE | NICKEL/GOLD (ENIG) | IMMERSION TIN | HARD GOLD | IN AN OPEN AREA | 1/4 OZ. | OPEN | NO | 6 | 8.0 MIL | X.X MIL | 08/16 MIL | NONE | DESIGN INFORMATION | ROGERS 4350B | 0.093" +/-10% | YES | TDR REPORTS/COUPONS | WHITE | GREEN | SOFT GOLD | TENTED | 1/2 OZ. | BOW & TWIST: | ORGANIC (OSP) | OTHER | WHERE INDICATED (SEE DRAWING) | YES - SEE TABLE 1 | ETCH | IDENTIFIER: | BLUE | RoHS | 1.0 OZ. | SILKSCREEN | PER SUPPLIED ARTWORK | ALL | ALL x MIL VIAS | ELECTRICAL TEST | UL 94V-0 | HASL | 2.0 OZ. | BREAK-AWAY | ENEPIG
User.10: FIGURE | SIZE | 8.0 | 10.0 | 28.0 | 37.0 | 38.0 | 91.0 | 23.62 | 33.46 | 67.0 | 125.0 | 27.56x23.62 | 27.56x27.56 | 74.8x23.62 | 78.74x27.56 | 33.46x19.69 | DRILL CHART: TOP to BOTTOM | ALL UNITS ARE IN MILS | TOLERANCE | +3.0/-8.0 | +3.0/-10.0 | +3.0/-3.0 | +1.18/-1.18 | +1.97/-1.97 | +2.0/-2.0 | PLATED | NON-PLATED | QTY | 26 | 123 | 5 | 4 | 14 | 2 | 1
